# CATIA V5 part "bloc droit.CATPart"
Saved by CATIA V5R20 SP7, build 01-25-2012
Part number: bloc patin droit
Bounding box of the stored display mesh (mm): x -1.04 to 7.96, y -69.75 to -65.25, z -2.561 to 1.919
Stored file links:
  F:\Travaux\Modélisations\CFAO_2011\CFAO_2011_MMS\CFAO_2011_MMS_DONE\CFAO_2011_MMS_jboiteux\Catia\bloc droit.CATPart
  U:\finthinkmotion\stepper.CATProduct
  F:\Travaux\Modélisations\CFAO_2011\CFAO_2011_MMS\CFAO_2011_MMS_DONE\CFAO_2011_MMS_jboiteux\Catia\support droit.CATPart
  F:\Travaux\Modélisations\CFAO_2011\CFAO_2011_MMS\CFAO_2011_MMS_DONE\CFAO_2011_MMS_jboiteux\Catia\bati.CATPart
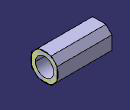
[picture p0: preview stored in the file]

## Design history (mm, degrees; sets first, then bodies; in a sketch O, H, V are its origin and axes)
Parameters
  rayontube = 9 mm {= External.royontubebati}
External parameters (linked from other documents)
  External.royontubebati = 9 mm
Set1
  DatumSurface1: linked copy from another document
  DatumCurve1: linked copy from another document
Body1 (main body)
  Sketch1 on face of DatumSurface1, origin (7.96, 0, 0), H (0, -1, 0), V (0, 0, 1)
    circle A1 centre (67.5, -0.321) radius 1.5
    point P1 (67.5, -0.321)
    line L1 (65.4, 1.779) -> (69.6, 1.779)
    line L2 (69.6, 1.779) -> (69.6, -2.421)
    line L3 (69.6, -2.421) -> (65.4, -2.421)
    line L4 (65.4, -2.421) -> (65.4, 1.779)
    reference projected circle E1 centre (67.5, -0.321) radius 1.5 from edge of DatumCurve1
    radius A1 = 1.5 {= rayontube /3/2}
    distance L1 P1 = 2.1 {= rayontube /30*7}
    distance L4 P1 = 2.1 {= rayontube /30*7}
    distance P1 L3 = 2.1 {= rayontube /30*7}
    distance P1 L2 = 2.1 {= rayontube /30*7}
    horizontal: L1 H, L3 H
    vertical: L2 V, L4 V
    concentricity: E1 A1
  Pad1: profile Sketch1, direction (-1, 0, 0), length 9 {= rayontube}
  Chamfer1: length 1 {= rayontube /9}, angle 45, on edge [face of Pad1 from Sketch1.L2 | face of Pad1 from Sketch1.L3]; edge [face of Pad1 from Sketch1.L3 | face of Pad1 from Sketch1.L4]; edge [face of Pad1 from Sketch1.L1 | face of Pad1 from Sketch1.L2]; edge [face of Pad1 from Sketch1.L4 | face of Pad1 from Sketch1.L1]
